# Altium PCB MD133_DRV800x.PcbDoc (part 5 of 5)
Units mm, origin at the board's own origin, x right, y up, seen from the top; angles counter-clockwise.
Board outline 152.66 x 101.89 mm, 4 copper layers (Top Layer, Mid-Layer 1, Mid-Layer 2, Bottom Layer), stack 2.355 mm thick; 306 components, 166 nets, 1010 pads, 1623 vias.
Unrouted connection lines stored in the file: 4.
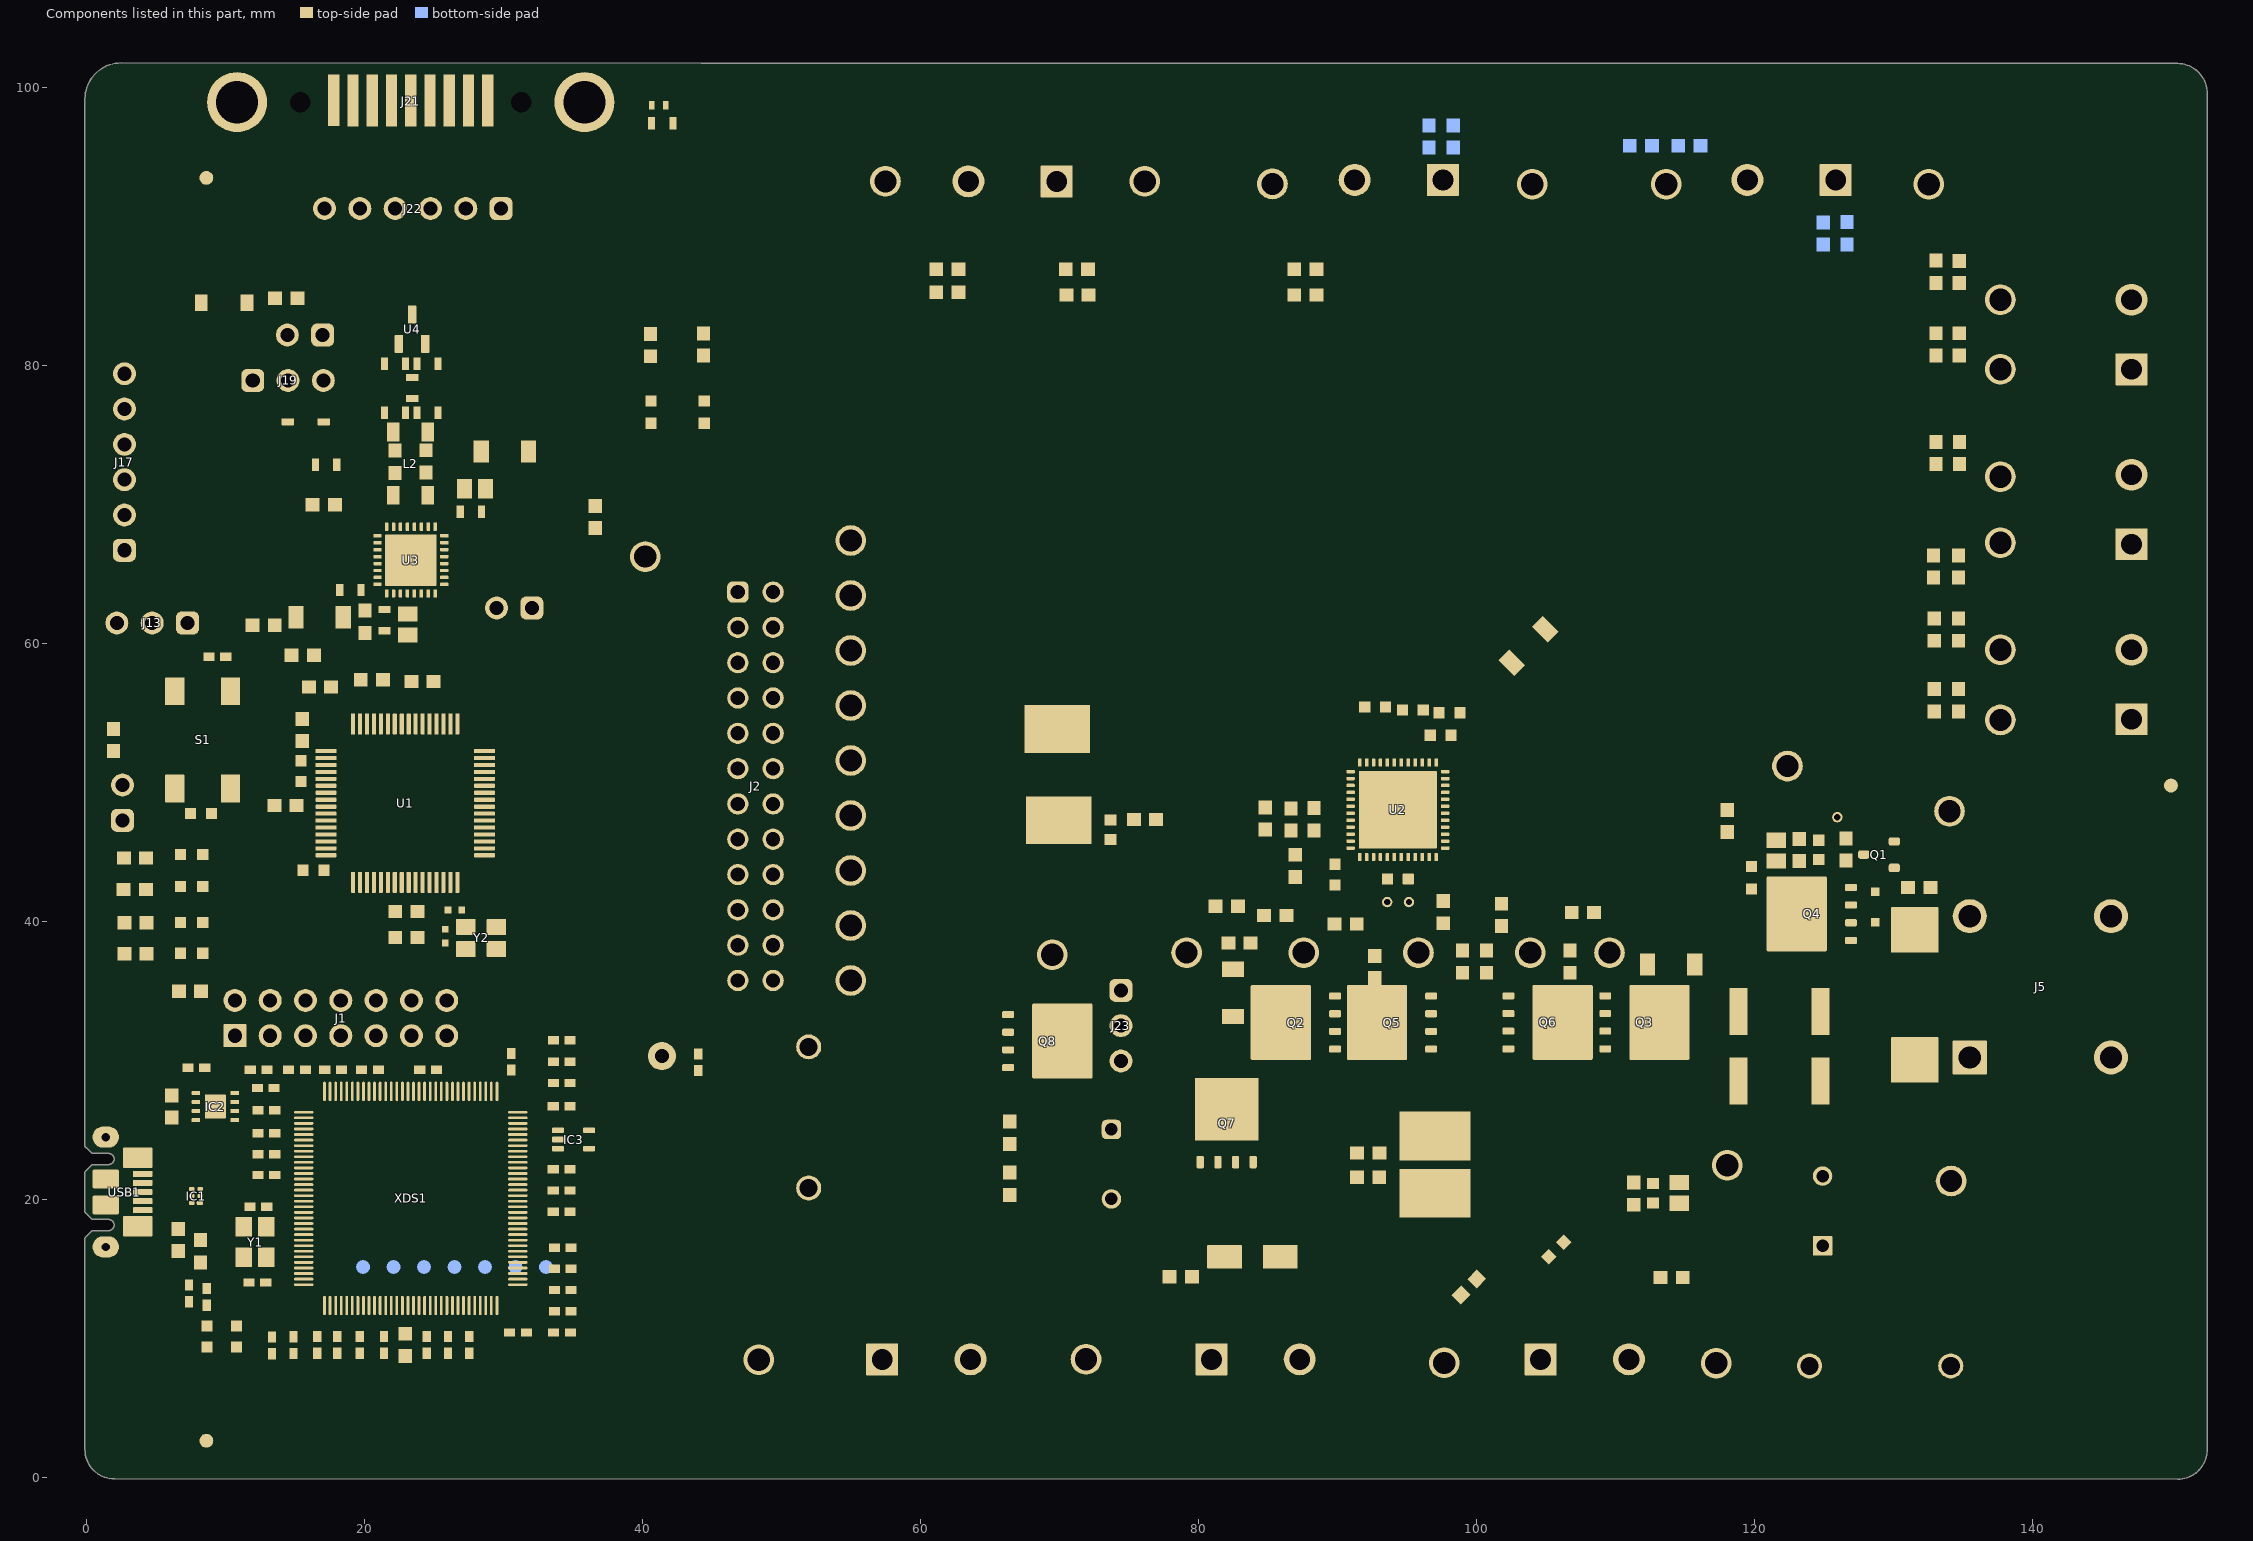
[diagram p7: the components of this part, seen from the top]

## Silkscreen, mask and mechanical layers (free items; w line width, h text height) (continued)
M10 Fab Notes:
  drawing of 189 lines, arcs and shapes, not listed
  text "DESIGN INFORMATION" at 314.163,161.447 h1.52
  text "MIN. TRACK WIDTH:" at 297.791,158.091 h1.52
  text "8" at 325.636,158.091 h1.52
  text "MIL" at 329.567,158.091 h1.52
  text "7.874" at 321.41,155 h1.52
  text "MIN. CLEARANCE:" at 297.791,154.938 h1.52
  text "MIL" at 329.567,154.938 h1.52
  text "MIN. VIA PAD SIZE:" at 297.791,151.785 h1.52
  text "24" at 324.874,151.785 h1.52
  text "MIL" at 329.567,151.785 h1.52
  text "0.05mm (2MIL)" at 315.444,148.486 h1.52
  text "MINIMUM ANNULAR RING" at 289.429,148.277 h1.52
  text "EXTERNAL" at 333.428,148.277 h1.52
  text "PER" at 294.509,145.48 h1.52
  text "IPC-D-275 CLASS 2 LEVEL C" at 300.097,145.48 h1.52
  text "MIL, HOLES" at 337.898,142.928 h1.52
  text "+/-" at 327.93,142.709 h1.52
  text "+/-" at 349.621,142.709 h1.52
  text "REGISTRATION TOLERANCES:" at 289.429,142.682 h1.52
  text "METAL" at 319.903,142.682 h1.52
  text "5" at 334.539,142.683 h1.52
  text "3" at 355.697,142.683 h1.52
  text "MIL" at 358.65,142.682 h1.52
  text "HOLE SIZE TOLERANCE (UNLESS OTHERWISE SPECIFIED):" at 289.429,140.185 h1.52
  text "+/-" at 349.621,140.112 h1.52
  text "3" at 355.697,140.085 h1.52
  text "MIL" at 358.65,140.085 h1.52
  text "MATERIAL:" at 287.53,136.589 h1.52
  text "FR-4 High Tg" at 312.586,133.324 h1.52
  text "X" at 308.917,133.122 h1.52
  text "FR-4" at 298.223,133.007 h1.52
  text "OTHER" at 336.018,133.007 h1.52
  text "62 MIL (1.6mm) +/-10%" at 306.354,129.374 h1.52
  text "X" at 303.303,129.312 h1.52
  text "THICKNESS:" at 289.429,129.165 h1.52
  text "OTHER" at 338.99,129.165 h1.52
  text "TOLERANCE:" at 289.429,125.652 h1.52
  text "X" at 310.974,125.652 h1.52
  text "ANSI IPC-6012 TYPE 3 CLASS 2" at 315.496,125.652 h1.52
  text "OTHER +/-" at 315.495,121.989 h1.52
  text "BOW & TWIST:" at 289.429,118.302 h1.52
  text "X" at 310.974,118.302 h1.52
  text "ANSI IPC-6012 TYPE 3 CLASS 2" at 315.496,118.302 h1.52
  text "OTHER +/-" at 315.495,114.576 h1.52
  text "DRILLING:" at 287.53,111.258 h1.52
  text "NC_DRILL FILES" at 332.259,108.586 h1.52
  text "REFERENCE:" at 289.429,108.486 h1.52
  text "X" at 306.123,108.484 h1.52
  text "AS SHOWN" at 310.644,108.486 h1.52
  text "X" at 329.008,108.486 h1.52
  text "OTHER" at 339.828,104.873 h1.52
  text "PTH COPPER THICKNESS:" at 289.421,104.783 h1.52
  text "X" at 318.357,104.783 h1.52
  text "20-30 um" at 321.608,104.783 h1.52
  text "BOARD FINISH:" at 287.53,101.034 h1.52
  text "SILKSCREEN:" at 291.473,98.237 h1.52
  text "X" at 315.8,98.237 h1.52
  text "TOP" at 318.772,98.237 h1.52
  text "X" at 328.754,98.237 h1.52
  text "BOTTOM" at 331.751,98.237 h1.52
  text "SILKSCREEN COLOR:" at 291.473,94.295 h1.52
  text "X" at 315.775,94.295 h1.52
  text "WHITE" at 318.772,94.295 h1.52
  text "OTHER" at 331.751,94.295 h1.52
  text "X" at 319.102,90.652 h1.52
  text "GREEN" at 322.099,90.652 h1.52
  text "OTHER" at 337.796,90.652 h1.52
  text "SOLDER RESIST COLOR:" at 291.473,90.477 h1.52
  text "X" at 319.102,86.734 h1.52
  text "MATTE" at 322.099,86.734 h1.52
  text "SEMI-GLOSS" at 337.785,86.717 h1.52
  text "IMMERSION GOLD (ENIG)" at 314.479,82.345 h1.52
  text "ENEPIG" at 348.453,82.162 h1.52
  text "SURFACE FINISH:" at 287.53,82.136 h1.52
  text "X" at 309.958,82.136 h1.52
  text "IMM. TIN/SILVER OR EQUIV" at 295.9,78.649 h1.52
  text "OTHER" at 332.259,78.549 h1.52
  text "ARRAY/PANEL:" at 287.53,74.602 h1.52
  text "CUT AND TRIM PER M1 BOARD OUTLINE" at 314.479,74.393 h1.52
  text "N.C. ROUTE" at 314.479,70.94 h1.52
  text "X" at 331.955,70.94 h1.52
  text "V. SCORE" at 336.476,70.94 h1.52
  text "CERTIFICATION:" at 287.53,67.66 h1.52
  text "MATERIALS AND WORKMANSHIP FOR ALL PCBS" at 305.945,67.66 h1.52
  text "TO MEET OR EXCEED THE REQUIREMENTS OF:" at 305.945,65.271 h1.52
  text "X" at 296.738,62.003 h1.52
  text "ANSI IPC-A-600F CLASS ->" at 299.989,62.003 h1.52
  text "X" at 341.848,62.003 h1.52
  text "2" at 344.642,62.003 h1.52
  text "1" at 336.641,61.965 h1.52
  text "3" at 353.633,61.965 h1.52
  text "X" at 317.362,58.252 h1.52
  text "RoHS" at 320.613,58.252 h1.52
  text "OTHER" at 336.981,58.252 h1.52
  text "PER ORDER" at 347.067,58.252 h1.52
  text "ALL BOARDS MUST MEET OR EXCEED UL94-V0 REQUIREMENTS." at 288.229,54.345 h1.52
  text "PCB MUST BEAR THE UL94V-0 UL REGISTERED MATERIAL ID NUMBER" at 288.229,51.397 h1.52
  text "ADDITIONAL REQUIREMENTS:" at 287.53,47.094 h1.52
  text "MICROSECTION:" at 289.429,44.373 h1.52
  text "YES" at 312.435,44.373 h1.52
  text "REQUIRED" at 334.317,40.707 h1.52
  text "BARE BOARD ELEC. TEST:" at 289.429,40.634 h1.52
  text "NONE" at 322.595,40.634 h1.52
  text "X" at 331.32,40.634 h1.52
  text "PER ORDER" at 349.353,40.634 h1.52
  text "XX MIL VIAS REQUIRE NON-CONDUCTIVE FILL AND PLANARIZE" at 293.7,35.428 h1.5
  text "XX MIL VIAS REQUIRE CONDUCTIVE FILL AND PLANARIZE" at 293.903,32.787 h1.52
  text "OUTER XX MIL TRACES REQUIRE 50 OHM SINGLE-ENDED IMPEDANCE" at 293.878,28.637 h1.47
  text "LAYER 2 & 3 (INNER LAYERS) XX MIL WIDE, XX MIL SPACE / TRACES REQUIRE 100 OHM DIFFERENTIAL IMPEDANCE" at 293.675,22.65 h1.52
  text ".Layer_Name" at 14.316,-21.806 h1.52
M11 Gerber Information:
  lines w0.254: -7.757,-23.626 159.883,-23.626 ; -7.757,-18.462 159.934,-18.462 ; -7.757,-13.297 -7.757,-28.791 93.97,-28.791 159.934,-28.791 159.934,-13.297 -7.744,-13.297 -7.744,-28.791 32.274,-28.791 ; 54.854,-28.791 54.854,-13.297 ; 87.036,-18.462 87.036,-13.297 ; 108.372,-18.462 108.372,-13.297 ; 124.171,-28.956 124.171,-23.804
  text "ALL ARTWORK VIEWED FROM TOP SIDE" at -6.144,-16.654 h1.52
  text "BOARD #:" at 56.759,-16.654 h1.52
  text ".PRJ_Number" at 70.615,-16.654 h1.52
  text "REV:" at 92.065,-16.654 h1.52
  text ".PCB_Rev" at 99.469,-16.654 h1.52
  text "SVN REV:" at 113.35,-16.654 h1.52
  text ".VersionControl_RevNumber" at 126.203,-16.654 h1.52
  text "LAYER NAME =" at -6.144,-21.806 h1.52
  text "TID #:" at 56.759,-21.819 h1.52
  text ".TID" at 70.615,-21.819 h1.52
  text "PLOT NAME =" at -6.144,-27.034 h1.52
  text ".plot_File_Name" at 14.316,-27.034 h1.52
  text "GENERATED    :" at 56.81,-27.034 h1.52
  text ".Print_Date" at 78.895,-27.034 h1.52
  text ".Print_Time" at 97.412,-27.034 h1.52
  text "TEXAS INSTRUMENTS" at 129.53,-27.034 h1.52
M12 Stackup:
  drawing of 295 lines, arcs and shapes, not listed
  text "Layer" at 20.309,155.27 h1.52
  text "Name" at 30.721,155.27 h1.52
  text "Material" at 54.337,155.27 h1.52
  text "Thickness" at 76.175,155.27 h1.52
  text "Constant" at 92.68,155.27 h1.52
  text "Board Layer Stack" at 107.155,155.27 h1.52
  text "Top Overlay" at 30.721,152.222 h1.52
  text "Top Solder" at 30.721,149.174 h1.52
  text "Solder Resist" at 54.337,149.174 h1.52
  text "0.40mil" at 76.175,149.174 h1.52
  text "3.5" at 92.68,149.174 h1.52
  text "1" at 20.309,146.126 h1.52
  text "Top Layer" at 30.721,146.126 h1.52
  text "2.76mil" at 76.175,146.126 h1.52
  text "Dielectric1" at 30.721,143.078 h1.52
  text "FR-4 High Tg" at 54.337,143.078 h1.52
  text "59.20mil" at 76.175,143.078 h1.52
  text "4.8" at 92.68,143.078 h1.52
  text "2" at 20.309,140.03 h1.52
  text "Mid-Layer 1" at 30.721,140.03 h1.52
  text "1.40mil" at 76.175,140.03 h1.52
  text "Dielectric2" at 30.721,136.982 h1.52
  text "FR-4" at 54.337,136.982 h1.52
  text "12.60mil" at 76.175,136.982 h1.52
  text "4.8" at 92.68,136.982 h1.52
  text "3" at 20.309,133.934 h1.52
  text "Mid-Layer 2" at 30.721,133.934 h1.52
  text "1.40mil" at 76.175,133.934 h1.52
  text "Dielectric3" at 30.721,130.886 h1.52
  text "FR-4" at 54.337,130.886 h1.52
  text "12.60mil" at 76.175,130.886 h1.52
  text "4.8" at 92.68,130.886 h1.52
  text "4" at 20.309,127.838 h1.52
  text "Bottom Layer" at 30.721,127.838 h1.52
  text "2.76mil" at 76.175,127.838 h1.52
  text "Bottom Solder" at 30.721,124.79 h1.52
  text "Solder Resist" at 54.337,124.79 h1.52
  text "0.40mil" at 76.175,124.79 h1.52
  text "3.5" at 92.68,124.79 h1.52
  text "Bottom Overlay" at 30.721,121.742 h1.52
  text ".Layer_Name" at 14.316,-21.806 h1.52
M13 Component Bodies Top:
  text ".Layer_Name" at 14.316,-21.806 h1.52
M14 Component Bodies Bottom:
  text ".Layer_Name" at 14.316,-21.806 h1.52
M15 Courtyards Top:
  text ".Layer_Name" at 14.316,-21.806 h1.52
M16 Courtyards Bottom:
  text ".Layer_Name" at 14.316,-21.806 h1.52
Drill Drawing:
  drawing of 152 lines, arcs and shapes, not listed
  text "Symbol" at 182.743,79.403 h1.83
  text "Quantity" at 190.376,79.403 h1.83
  text "Finished Hole Size" at 198.812,79.403 h1.83
  text "Plated" at 214.983,79.403 h1.83
  text "Hole Type" at 221.565,79.403 h1.83
  text "Drill Layer Pair" at 231.096,79.403 h1.83
  text "Hole Tolerance" at 249.498,79.403 h1.83
  text "2" at 190.376,76.245 h1.52
  text "59.00mil (1.499mm)" at 198.812,76.245 h1.52
  text "NPTH" at 214.983,76.245 h1.52
  text "Round" at 221.565,76.245 h1.52
  text "Top Layer - Bottom Layer" at 231.096,76.245 h1.52
  text "C" at 182.101,75.991 h1.4
  text "1557" at 190.376,73.088 h1.52
  text "7.87mil (0.200mm)" at 198.812,73.088 h1.52
  text "PTH" at 214.983,73.088 h1.52
  text "Round" at 221.565,73.088 h1.52
  text "Top Layer - Bottom Layer" at 231.096,73.088 h1.52
  text "51" at 190.376,69.93 h1.52
  text "8.00mil (0.203mm)" at 198.812,69.93 h1.52
  text "PTH" at 214.983,69.93 h1.52
  text "Round" at 221.565,69.93 h1.52
  text "Top Layer - Bottom Layer" at 231.096,69.93 h1.52
  text "10" at 190.376,66.773 h1.52
  text "14.00mil (0.356mm)" at 198.812,66.773 h1.52
  text "PTH" at 214.983,66.773 h1.52
  text "Round" at 221.565,66.773 h1.52
  text "Top Layer - Bottom Layer" at 231.096,66.773 h1.52
  text "1" at 190.376,63.615 h1.52
  text "16.00mil (0.406mm)" at 198.812,63.615 h1.52
  text "PTH" at 214.983,63.615 h1.52
  text "Round" at 221.565,63.615 h1.52
  text "Top Layer - Bottom Layer" at 231.096,63.615 h1.52
  text "3" at 190.376,60.457 h1.52
  text "17.72mil (0.450mm)" at 198.812,60.457 h1.52
  text "PTH" at 214.983,60.457 h1.52
  text "Round" at 221.565,60.457 h1.52
  text "Top Layer - Bottom Layer" at 231.096,60.457 h1.52
  text "B" at 182.101,60.204 h1.4
  text "4" at 190.376,57.3 h1.52
  text "35.43mil (0.900mm)" at 198.812,57.3 h1.52
  text "PTH" at 214.983,57.3 h1.52
  text "Round" at 221.565,57.3 h1.52
  text "Top Layer - Bottom Layer" at 231.096,57.3 h1.52
  text "42" at 190.376,54.142 h1.52
  text "40.00mil (1.016mm)" at 198.812,54.142 h1.52
  text "PTH" at 214.983,54.142 h1.52
  text "Round" at 221.565,54.142 h1.52
  text "Top Layer - Bottom Layer" at 231.096,54.142 h1.52
  text "24" at 190.376,50.985 h1.52
  text "40.16mil (1.020mm)" at 198.812,50.985 h1.52
  text "PTH" at 214.983,50.985 h1.52
  text "Round" at 221.565,50.985 h1.52
  text "Top Layer - Bottom Layer" at 231.096,50.985 h1.52
  text "4" at 190.376,47.827 h1.52
  text "51.18mil (1.300mm)" at 198.812,47.827 h1.52
  text "PTH" at 214.983,47.827 h1.52
  text "Round" at 221.565,47.827 h1.52
  text "Top Layer - Bottom Layer" at 231.096,47.827 h1.52
  text "18" at 190.376,44.67 h1.52
  text "59.06mil (1.500mm)" at 198.812,44.67 h1.52
  text "PTH" at 214.983,44.67 h1.52
  text "Round" at 221.565,44.67 h1.52
  text "Top Layer - Bottom Layer" at 231.096,44.67 h1.52
  text "4" at 190.376,41.512 h1.52
  text "62.99mil (1.600mm)" at 198.812,41.512 h1.52
  text "PTH" at 214.983,41.512 h1.52
  text "Round" at 221.565,41.512 h1.52
  text "Top Layer - Bottom Layer" at 231.096,41.512 h1.52
  text "36" at 190.376,38.355 h1.52
  text "63.00mil (1.600mm)" at 198.812,38.355 h1.52
  text "PTH" at 214.983,38.355 h1.52
  text "Round" at 221.565,38.355 h1.52
  text "Top Layer - Bottom Layer" at 231.096,38.355 h1.52
  text "2" at 190.376,35.197 h1.52
  text "120.00mil (3.048mm)" at 198.812,35.197 h1.52
  text "PTH" at 214.983,35.197 h1.52
  text "Round" at 221.565,35.197 h1.52
  text "Top Layer - Bottom Layer" at 231.096,35.197 h1.52
  text "A" at 182.101,34.943 h1.4
  text "3" at 190.376,32.04 h1.52
  text "169.29mil (4.300mm)" at 198.812,32.04 h1.52
  text "PTH" at 214.983,32.04 h1.52
  text "Round" at 221.565,32.04 h1.52
  text "Top Layer - Bottom Layer" at 231.096,32.04 h1.52
  text "1" at 190.376,28.882 h1.52
  text "177.17mil (4.500mm)" at 198.812,28.882 h1.52
  text "PTH" at 214.983,28.882 h1.52
  text "Round" at 221.565,28.882 h1.52
  text "Top Layer - Bottom Layer" at 231.096,28.882 h1.52
  text "2" at 190.376,25.725 h1.52
  text "23.62mil (0.600mm)" at 198.812,25.725 h1.52
  text "PTH" at 214.983,25.725 h1.52
  text "Slot" at 221.565,25.725 h1.52
  text "Top Layer - Bottom Layer" at 231.096,25.725 h1.52
  text "1764 Total" at 190.376,22.567 h1.52
  text "Slot definitions :" at 182.743,20.357 h1.52
  text "Routed Path Length" at 194.191,20.357 h1.52
  text "= Calculated from tool start centre position to tool end centre position." at 207.905,20.357 h1.52
  text "Hole Length" at 194.191,19.094 h1.52
  text "= Routed Path Length + Tool Size = Slot length as defined in the PCB layout" at 202.828,19.094 h1.52
  text ".Layer_Name" at 14.316,-21.806 h1.52
M17 Embedded Cavity:
  text ".Layer_Name" at 14.316,-21.806 h1.52
M18 Embedded Assembly:
  text ".Layer_Name" at 14.316,-21.806 h1.52
M19 Embedded Keepout:
  text ".Layer_Name" at 14.316,-21.806 h1.52

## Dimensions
-0.34,-10.16 to 25.06,-10.16 on M2 Board Dimensions
-0.34,0 to -0.13,17.22 on M2 Board Dimensions
-0.34,0 to -0.127,15.278 on M2 Board Dimensions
